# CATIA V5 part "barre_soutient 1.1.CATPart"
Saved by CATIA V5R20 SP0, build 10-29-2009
Part number: barre_soutient 1.1
Bounding box of the stored display mesh (mm): x 460.778 to 500.778, y 114.223 to 258.146, z 82.455 to 1081.183
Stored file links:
  C:\Users\Mike-7\Desktop\MMS_GR3\bfoltzer\CFAO_bfoltzer\barre_soutient 1.1.CATPart
  D:\ecole\thinkmotion\Eolienne.CATProduct
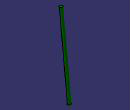
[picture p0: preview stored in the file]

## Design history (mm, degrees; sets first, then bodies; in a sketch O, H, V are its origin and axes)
Set1
  Plane1 "plan de bout de barre": linked copy from another document
  Point1: linked copy from another document
  Point2: linked copy from another document
  Plane2 "Plan de bout de barre": linked copy from another document
Body1 (main body)
  Sketch1 on Plane1, origin (0, 131.1458, 73.3225), H (-1, 0, 0), V (0, -0.9946, -0.1041)
    circle A1 centre (-480.7782, -107.6941) radius 20
    point P1 (-480.7782, -107.6941)
    reference projected point E1 (-480.7782, -107.6941) from Point1
    reference projected point E2 (-480.7782, -127.6941) from Point2
    coincidence: P1 E1, E2 A1
  Pad1: profile Sketch1, direction (0, -0.1041, 0.9946), up to Plane2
